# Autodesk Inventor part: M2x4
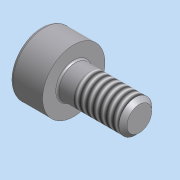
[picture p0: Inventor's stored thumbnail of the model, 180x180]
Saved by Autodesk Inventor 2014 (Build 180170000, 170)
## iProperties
Company: 한국ATC센터
Created: 2015-05
Part Number: M2x4
Document SubType Name: 모델링
Designer: KYOUNG IL JANG
Vendor: CBT Solutions
Material: 일반
Appearance: 기본값
d0: 1.000 ul
Author: KYOUNG IL JANG
Comments: 파생
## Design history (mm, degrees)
node "KS B 1003 - 미터 M 2 x 4" dims count "d0" = 1
node "솔리드1"
node "솔리드 본체"
node "곡면 본체"
feature "Solid1::KS B 1003 - 미터 M 2 x 4" dims count "d0" = 1
tag "피쳐 태그1"
